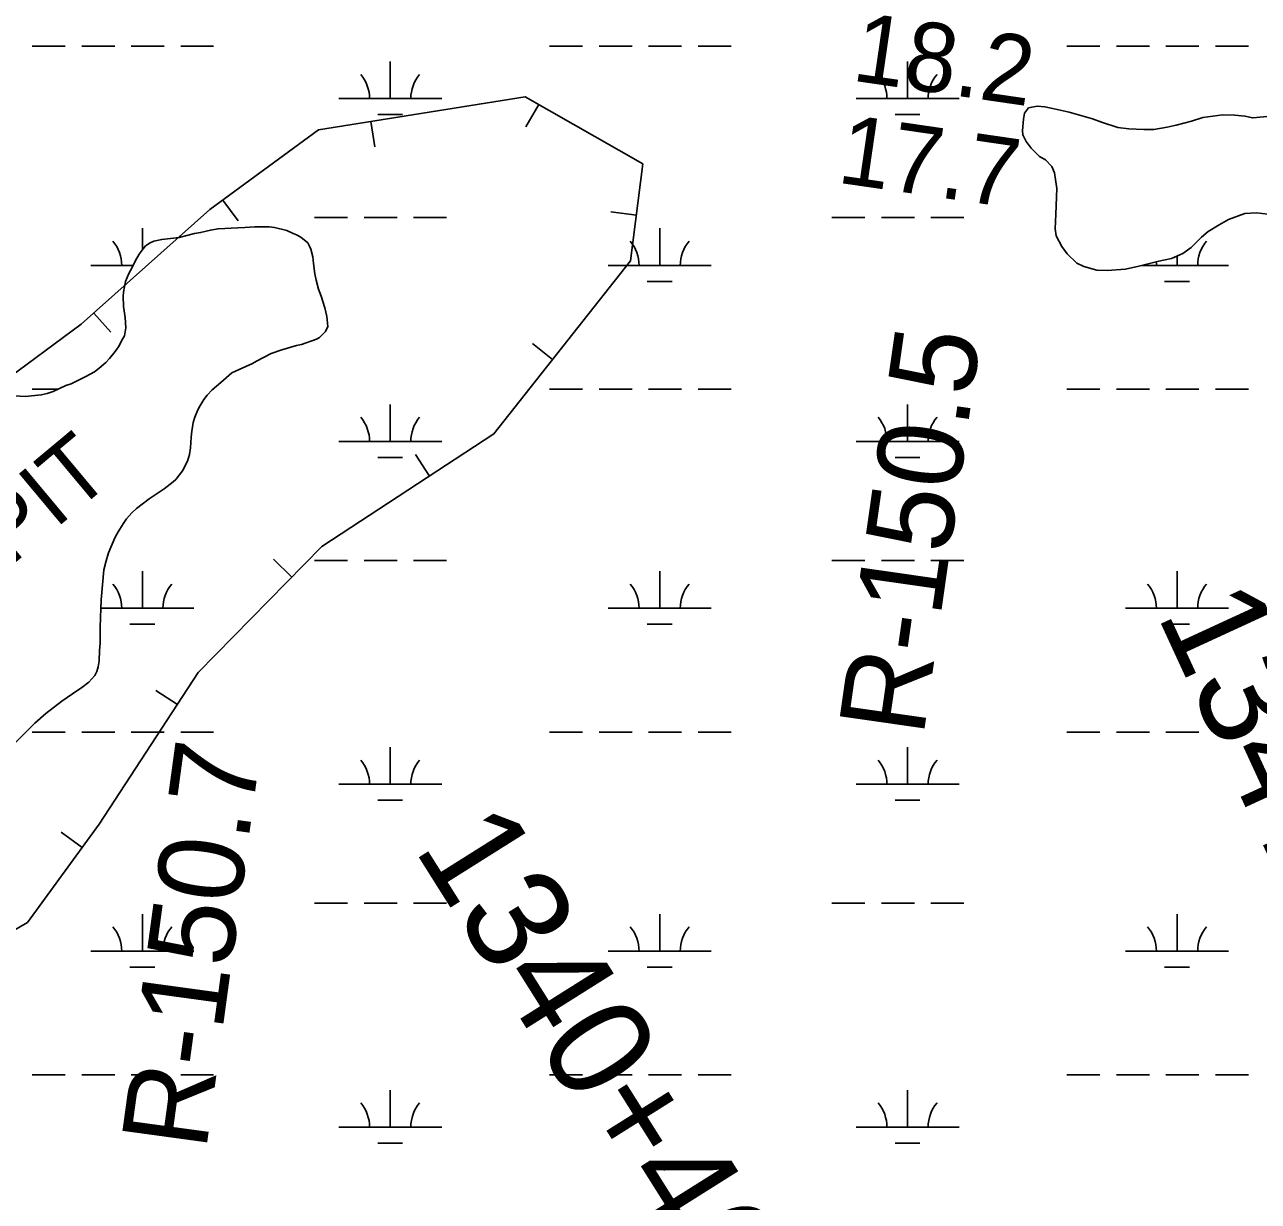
# Model space of a CAD drawing. Extents: x 3445503 to 3483459, y 540493 to 566012.
# Drawn here: x 3468436 to 3469633, y 548187 to 549328 of the extents above; entities that cross this region are included whole.
import ezdxf

# ---------------------------------------------------------------- set-up
doc = ezdxf.new("R2010")
doc.units = 0
for name, color, linetype in [('V-BORW-IDEN', 7, 'Continuous'), ('V-BORW-LINE', 7, 'Continuous'), ('V-RIVR-RANG', 7, 'Continuous'), ('V-RIVR-RANG-IDEN', 7, 'Continuous'), ('V-SITE-VEGE', 7, 'Continuous'), ('V-SURV-IDEN', 7, 'Continuous'), ('V-WETL-SWMP', 7, 'Continuous')]:
    doc.layers.add(name, color=color, linetype=linetype)

msp = doc.modelspace()

# ---------------------------------------------------------------- linework, layer by layer
at = {"layer": 'V-BORW-LINE'}
for p, q in [((3468934.5, 549250.7), (3468922.1, 549229)), ((3468771.8, 549234.3), (3468775.7, 549209.6)), ((3468628.1, 549158.1), (3468642.9, 549137.9)), ((3469029.3, 549143.4), (3469004.5, 549146.6)), ((3468502.8, 549048.5), (3468519.4, 549029.8)), ((3468948, 549003.4), (3468928.4, 549018.9)), ((3468828.6, 548890.3), (3468814.9, 548911.2)), ((3468694.9, 548792.1), (3468677.1, 548809.6)), ((3468584, 548668.6), (3468563, 548682.3)), ((3468491.6, 548529.9), (3468471.4, 548544.7))]:
    msp.add_line(p, q, dxfattribs=at)
for points in [[(3468333.1, 548921.3), (3468490.6, 549037.6), (3468615.6, 549148.9), (3468720.8, 549226.1), (3468921.3, 549258.2), (3469035.7, 549193.1), (3469023.6, 549099.2), (3468891.1, 548931.2), (3468724.2, 548822), (3468604.3, 548699.7), (3468508.1, 548552.5), (3468438.6, 548457.1), (3468325.2, 548391.8)], [(3468325.2, 548391.8), (3468438.6, 548457.1), (3468508.1, 548552.5), (3468604.3, 548699.7), (3468724.2, 548822), (3468891.1, 548931.2), (3469023.6, 549099.2), (3469035.7, 549193.1), (3468921.3, 549258.2), (3468720.8, 549226.1), (3468615.6, 549148.9), (3468490.6, 549037.6), (3468333.1, 548921.3)]]:
    msp.add_lwpolyline(points, dxfattribs=at)
at = {"layer": 'V-SITE-VEGE'}
for points in [[(3469668.4, 549241.9), (3469627.2, 549237.8), (3469619.6, 549239.5), (3469609.9, 549240.3), (3469598.2, 549240.7), (3469579, 549238.1), (3469567.8, 549234.7), (3469553, 549230.8), (3469544.2, 549228.8), (3469531.2, 549226.7), (3469521.7, 549226.6), (3469507.1, 549227.2), (3469496.5, 549228.6), (3469480.6, 549233.6), (3469471.9, 549236.8), (3469449.1, 549243.5), (3469434.7, 549246.5), (3469425.5, 549248.6), (3469418.2, 549249.2), (3469409.8, 549247.6), (3469405.9, 549242.5), (3469404.8, 549236.7), (3469404, 549225.7), (3469404.3, 549221.3), (3469407.6, 549214.9), (3469412.3, 549208.3), (3469420.5, 549200.4), (3469426.1, 549197.2), (3469432.3, 549190.6), (3469435, 549184.4), (3469437.3, 549169.4), (3469436.2, 549144.5), (3469435.7, 549130.1), (3469436.6, 549123.5), (3469442, 549113.1), (3469447.1, 549105.9), (3469456.5, 549096.9), (3469463.3, 549093.7), (3469476, 549090), (3469485.9, 549089.6), (3469503.8, 549090.9), (3469516.6, 549093.9), (3469536, 549098.7), (3469548.3, 549101.4), (3469559.3, 549106.3), (3469567.6, 549112.2), (3469577.5, 549122.2), (3469584.1, 549127.7), (3469594.6, 549134.2), (3469603.6, 549139.2), (3469619.5, 549145), (3469631, 549145.8), (3469647.3, 549143.9)], [(3468716.1, 549096.6), (3468715.4, 549103), (3468713.5, 549110.5), (3468712.2, 549113.5), (3468710.4, 549116.6), (3468703.7, 549122.1), (3468699.7, 549124.3), (3468696.2, 549125.6), (3468690.2, 549128.4), (3468678.2, 549131.4), (3468672.9, 549132.2), (3468659, 549132.1), (3468649.5, 549131.4), (3468642.7, 549131.3), (3468623.5, 549130.3), (3468616, 549128.9), (3468606.5, 549126.6), (3468600.6, 549125.7), (3468585.6, 549121.8), (3468568.8, 549119.9), (3468561.1, 549118.3), (3468557.6, 549116.7), (3468553.2, 549113.6), (3468550.8, 549110.7), (3468546.8, 549105.6), (3468543.4, 549099.6), (3468540.1, 549092.7), (3468536.8, 549086.8), (3468533.6, 549079), (3468532.7, 549073.9), (3468531.7, 549068.6), (3468531.5, 549064.9), (3468531.6, 549054.9), (3468533.2, 549044.1), (3468533.9, 549034), (3468532.7, 549026.4), (3468530.9, 549023.1), (3468526.8, 549015.8), (3468523.7, 549011.1), (3468518.3, 549004.2), (3468514.6, 549000.5), (3468508.2, 548994.9), (3468503.6, 548991.5), (3468495.2, 548986.8), (3468480.9, 548979.9), (3468475.9, 548978.1), (3468463.5, 548972.2), (3468457.8, 548970.4), (3468451.9, 548969), (3468436.4, 548967.4), (3468426, 548968)], [(3468424.1, 548628.8), (3468445.8, 548650.4), (3468456.3, 548659.9), (3468471.9, 548672), (3468482.2, 548678.9), (3468491.2, 548685.2), (3468498, 548690.3), (3468503.9, 548696.7), (3468505.7, 548700.5), (3468507, 548705.2), (3468508.2, 548711.1), (3468508.6, 548720.9), (3468509, 548728.1), (3468509.1, 548737.9), (3468509.1, 548743.4), (3468509.4, 548753.1), (3468509.6, 548761.3), (3468510, 548770.3), (3468512.8, 548799.3), (3468515, 548808.1), (3468517.3, 548815.7), (3468519.7, 548821.9), (3468523.8, 548830.9), (3468526.5, 548836.3), (3468531.3, 548844), (3468534.5, 548848.9), (3468539.8, 548854.5), (3468544.2, 548858.9), (3468556.7, 548868.3), (3468565.2, 548874.1), (3468571.2, 548877.9), (3468580, 548884.8), (3468582.4, 548887.1), (3468588.9, 548895.5), (3468593.7, 548904.8), (3468595.6, 548911.2), (3468596.7, 548917.6), (3468597.3, 548928), (3468597.9, 548934), (3468599.4, 548942.4), (3468600.9, 548947.5), (3468603.9, 548954.4), (3468605.9, 548958.1), (3468609.6, 548964.6), (3468612.9, 548968.8), (3468617.9, 548974.1), (3468626, 548981), (3468636.7, 548990.4), (3468643.8, 548993.8), (3468657, 548999.4), (3468660.9, 549001.8), (3468675, 549009.2), (3468685.2, 549012.6), (3468699.5, 549016.9), (3468704.3, 549017.9), (3468719.1, 549023.1), (3468721.9, 549024.6), (3468727.8, 549030.6), (3468729.8, 549035.3), (3468729.1, 549045.2), (3468727, 549053.4), (3468723.6, 549064.8), (3468720.9, 549071.7), (3468718.6, 549080.5), (3468717.5, 549086.6), (3468716.1, 549096.6)]]:
    msp.add_lwpolyline(points, dxfattribs=at)
at = {"layer": 'V-WETL-SWMP'}
for p, q in [((3468443.2, 549307.3), (3468475.2, 549307.3)), ((3468491.2, 549307.3), (3468523.2, 549307.3)), ((3468539.2, 549307.3), (3468571.2, 549307.3)), ((3468587.2, 549307.3), (3468619.2, 549307.3)), ((3468945.1, 549307.3), (3468977.1, 549307.3)), ((3468993.1, 549307.3), (3469025.1, 549307.3)), ((3469041.1, 549307.3), (3469073.1, 549307.3)), ((3469089.1, 549307.3), (3469121.1, 549307.3)), ((3469447, 549307.3), (3469479, 549307.3)), ((3469495, 549307.3), (3469527, 549307.3)), ((3469543, 549307.3), (3469575, 549307.3)), ((3469591, 549307.3), (3469623, 549307.3)), ((3468790.5, 549256.5), (3468790.5, 549292.5)), ((3469292.4, 549256.5), (3469292.4, 549292.5)), ((3468740.5, 549256.5), (3468840.5, 549256.5)), ((3469242.4, 549256.5), (3469342.4, 549256.5)), ((3468778.5, 549241.1), (3468802.5, 549241.1)), ((3469280.4, 549241.1), (3469304.4, 549241.1)), ((3468717.1, 549141.1), (3468749.1, 549141.1)), ((3468765.1, 549141.1), (3468797.1, 549141.1)), ((3468813.1, 549141.1), (3468845.1, 549141.1)), ((3469219, 549141.1), (3469251, 549141.1)), ((3469267, 549141.1), (3469299, 549141.1)), ((3469315, 549141.1), (3469347, 549141.1)), ((3468550, 549109.7), (3468550, 549130.7)), ((3469051.9, 549094.7), (3469051.9, 549130.7)), ((3468500, 549094.7), (3468541, 549094.7)), ((3469001.9, 549094.7), (3469101.9, 549094.7)), ((3469519.8, 549094.7), (3469603.8, 549094.7)), ((3469553.8, 549094.7), (3469553.8, 549103.9)), ((3469039.9, 549079.2), (3469063.9, 549079.2)), ((3469541.8, 549079.2), (3469565.8, 549079.2)), ((3468443.2, 548974.6), (3468468.5, 548974.6)), ((3468618.4, 548974.6), (3468619.2, 548974.6)), ((3468945.1, 548974.6), (3468977.1, 548974.6)), ((3468993.1, 548974.6), (3469025.1, 548974.6)), ((3469041.1, 548974.6), (3469073.1, 548974.6)), ((3469089.1, 548974.6), (3469121.1, 548974.6)), ((3469447, 548974.6), (3469479, 548974.6)), ((3469495, 548974.6), (3469527, 548974.6)), ((3469543, 548974.6), (3469575, 548974.6)), ((3469591, 548974.6), (3469623, 548974.6)), ((3468790.5, 548923.8), (3468790.5, 548959.8)), ((3469292.4, 548923.8), (3469292.4, 548959.8)), ((3468740.5, 548923.8), (3468840.5, 548923.8)), ((3469242.4, 548923.8), (3469342.4, 548923.8)), ((3468778.5, 548908.4), (3468802.5, 548908.4)), ((3469280.4, 548908.4), (3469304.4, 548908.4)), ((3468717.1, 548808.4), (3468749.1, 548808.4)), ((3468765.1, 548808.4), (3468797.1, 548808.4)), ((3468813.1, 548808.4), (3468845.1, 548808.4)), ((3469219, 548808.4), (3469251, 548808.4)), ((3469267, 548808.4), (3469299, 548808.4)), ((3469315, 548808.4), (3469347, 548808.4)), ((3468550, 548762), (3468550, 548798)), ((3469051.9, 548762), (3469051.9, 548798)), ((3469553.8, 548762), (3469553.8, 548798)), ((3468509.6, 548762), (3468600, 548762)), ((3469001.9, 548762), (3469101.9, 548762)), ((3469503.8, 548762), (3469603.8, 548762)), ((3468538, 548746.5), (3468562, 548746.5)), ((3469039.9, 548746.5), (3469063.9, 548746.5)), ((3469541.8, 548746.5), (3469565.8, 548746.5)), ((3468443.2, 548641.9), (3468475.2, 548641.9)), ((3468491.2, 548641.9), (3468523.2, 548641.9)), ((3468539.2, 548641.9), (3468571.2, 548641.9)), ((3468587.2, 548641.9), (3468619.2, 548641.9)), ((3468945.1, 548641.9), (3468977.1, 548641.9)), ((3468993.1, 548641.9), (3469025.1, 548641.9)), ((3469041.1, 548641.9), (3469073.1, 548641.9)), ((3469089.1, 548641.9), (3469121.1, 548641.9)), ((3469447, 548641.9), (3469479, 548641.9)), ((3469495, 548641.9), (3469527, 548641.9)), ((3469543, 548641.9), (3469575, 548641.9)), ((3469591, 548641.9), (3469623, 548641.9)), ((3468790.5, 548591.2), (3468790.5, 548627.2)), ((3469292.4, 548591.2), (3469292.4, 548627.2)), ((3468740.5, 548591.2), (3468840.5, 548591.2)), ((3469242.4, 548591.2), (3469342.4, 548591.2)), ((3468778.5, 548575.7), (3468802.5, 548575.7)), ((3469280.4, 548575.7), (3469304.4, 548575.7)), ((3468717.1, 548475.7), (3468749.1, 548475.7)), ((3468765.1, 548475.7), (3468797.1, 548475.7)), ((3468813.1, 548475.7), (3468845.1, 548475.7)), ((3469219, 548475.7), (3469251, 548475.7)), ((3469267, 548475.7), (3469299, 548475.7)), ((3469315, 548475.7), (3469347, 548475.7)), ((3468550, 548429.3), (3468550, 548465.3)), ((3469051.9, 548429.3), (3469051.9, 548465.3)), ((3469553.8, 548429.3), (3469553.8, 548465.3)), ((3468500, 548429.3), (3468600, 548429.3)), ((3469001.9, 548429.3), (3469101.9, 548429.3)), ((3469503.8, 548429.3), (3469603.8, 548429.3)), ((3468538, 548413.9), (3468562, 548413.9)), ((3469039.9, 548413.9), (3469063.9, 548413.9)), ((3469541.8, 548413.9), (3469565.8, 548413.9)), ((3468443.2, 548309.2), (3468475.2, 548309.2)), ((3468491.2, 548309.2), (3468523.2, 548309.2)), ((3468539.2, 548309.2), (3468571.2, 548309.2)), ((3468587.2, 548309.2), (3468619.2, 548309.2)), ((3468945.1, 548309.2), (3468977.1, 548309.2)), ((3468993.1, 548309.2), (3469025.1, 548309.2)), ((3469041.1, 548309.2), (3469073.1, 548309.2)), ((3469089.1, 548309.2), (3469121.1, 548309.2)), ((3469447, 548309.2), (3469479, 548309.2)), ((3469495, 548309.2), (3469527, 548309.2)), ((3469543, 548309.2), (3469575, 548309.2)), ((3469591, 548309.2), (3469623, 548309.2)), ((3468790.5, 548258.5), (3468790.5, 548294.5)), ((3469292.4, 548258.5), (3469292.4, 548294.5)), ((3468740.5, 548258.5), (3468840.5, 548258.5)), ((3469242.4, 548258.5), (3469342.4, 548258.5)), ((3468778.5, 548243.1), (3468802.5, 548243.1)), ((3469280.4, 548243.1), (3469304.4, 548243.1))]:
    msp.add_line(p, q, dxfattribs=at)
for points in [[(3469668.4, 549241.9), (3469627.2, 549237.8), (3469619.6, 549239.5), (3469609.9, 549240.3), (3469598.2, 549240.7), (3469579, 549238.1), (3469567.8, 549234.7), (3469553, 549230.8), (3469544.2, 549228.8), (3469531.2, 549226.7), (3469521.7, 549226.6), (3469507.1, 549227.2), (3469496.5, 549228.6), (3469480.6, 549233.6), (3469471.9, 549236.8), (3469449.1, 549243.5), (3469434.7, 549246.5), (3469425.5, 549248.6), (3469418.2, 549249.2), (3469409.8, 549247.6), (3469405.9, 549242.5), (3469404.8, 549236.7), (3469404, 549225.7), (3469404.3, 549221.3), (3469407.6, 549214.9), (3469412.3, 549208.3), (3469420.5, 549200.4), (3469426.1, 549197.2), (3469432.3, 549190.6), (3469435, 549184.4), (3469437.3, 549169.4), (3469436.2, 549144.5), (3469435.7, 549130.1), (3469436.6, 549123.5), (3469442, 549113.1), (3469447.1, 549105.9), (3469456.5, 549096.9), (3469463.3, 549093.7), (3469476, 549090), (3469485.9, 549089.6), (3469503.8, 549090.9), (3469516.6, 549093.9), (3469536, 549098.7), (3469548.3, 549101.4), (3469559.3, 549106.3), (3469567.6, 549112.2), (3469577.5, 549122.2), (3469584.1, 549127.7), (3469594.6, 549134.2), (3469603.6, 549139.2), (3469619.5, 549145), (3469631, 549145.8), (3469647.3, 549143.9)], [(3468617.9, 548974.1), (3468626, 548981), (3468636.7, 548990.4), (3468643.8, 548993.8), (3468657, 548999.4), (3468660.9, 549001.8), (3468675, 549009.2), (3468685.2, 549012.6), (3468699.5, 549016.9), (3468704.3, 549017.9), (3468719.1, 549023.1), (3468721.9, 549024.6), (3468727.8, 549030.6), (3468729.8, 549035.3), (3468729.1, 549045.2), (3468727, 549053.4), (3468723.6, 549064.8), (3468720.9, 549071.7), (3468718.6, 549080.5), (3468717.5, 549086.6), (3468716.1, 549096.6), (3468715.4, 549103), (3468713.5, 549110.5), (3468712.2, 549113.5), (3468710.4, 549116.6), (3468703.7, 549122.1), (3468699.7, 549124.3), (3468696.2, 549125.6), (3468690.2, 549128.4), (3468678.2, 549131.4), (3468672.9, 549132.2), (3468659, 549132.1), (3468649.5, 549131.4), (3468642.7, 549131.3), (3468623.5, 549130.3), (3468616, 549128.9), (3468606.5, 549126.6), (3468600.6, 549125.7), (3468585.6, 549121.8), (3468568.8, 549119.9), (3468561.1, 549118.3), (3468557.6, 549116.7), (3468553.2, 549113.6), (3468550.8, 549110.7), (3468546.8, 549105.6), (3468543.4, 549099.6), (3468540.1, 549092.7), (3468536.8, 549086.8), (3468533.6, 549079), (3468532.7, 549073.9), (3468531.7, 549068.6), (3468531.5, 549064.9), (3468531.6, 549054.9), (3468533.2, 549044.1), (3468533.9, 549034), (3468532.7, 549026.4), (3468530.9, 549023.1), (3468526.8, 549015.8), (3468523.7, 549011.1), (3468518.3, 549004.2), (3468514.6, 549000.5), (3468508.2, 548994.9), (3468503.6, 548991.5), (3468495.2, 548986.8), (3468480.9, 548979.9), (3468475.9, 548978.1), (3468463.5, 548972.2), (3468457.8, 548970.4), (3468451.9, 548969), (3468436.4, 548967.4), (3468426, 548968)], [(3468424.1, 548628.8), (3468445.8, 548650.4), (3468456.3, 548659.9), (3468471.9, 548672), (3468482.2, 548678.9), (3468491.2, 548685.2), (3468498, 548690.3), (3468503.9, 548696.7), (3468505.7, 548700.5), (3468507, 548705.2), (3468508.2, 548711.1), (3468508.6, 548720.9), (3468509, 548728.1), (3468509.1, 548737.9), (3468509.1, 548743.4), (3468509.5, 548753.1), (3468509.6, 548761.3), (3468510, 548770.3), (3468512.8, 548799.3), (3468515, 548808.1), (3468517.3, 548815.7), (3468519.7, 548821.9), (3468523.8, 548830.9), (3468526.5, 548836.3), (3468531.3, 548844), (3468534.5, 548848.9), (3468539.8, 548854.5), (3468544.2, 548858.9), (3468556.7, 548868.3), (3468565.2, 548874.1), (3468571.2, 548877.9), (3468580, 548884.8), (3468582.4, 548887.1), (3468588.9, 548895.5), (3468593.7, 548904.8), (3468595.6, 548911.2), (3468596.7, 548917.6), (3468597.3, 548928), (3468597.9, 548934), (3468599.4, 548942.4), (3468600.9, 548947.5), (3468603.9, 548954.4), (3468605.9, 548958.1), (3468609.6, 548964.6), (3468612.9, 548968.8), (3468617.9, 548974.1)]]:
    msp.add_lwpolyline(points, dxfattribs=at)
for centre, start, end in [((3468735.2, 549257), 359.2282, 40.7718), ((3468845.7, 549257), 139.2282, 180.7718), ((3469237.1, 549257), 359.2282, 40.7718), ((3469347.6, 549257), 139.2282, 180.7718), ((3468494.8, 549095.1), 359.2282, 40.7718), ((3468996.7, 549095.1), 359.2282, 40.7718), ((3469107.1, 549095.1), 139.2282, 180.7718), ((3469609.1, 549095.1), 139.2282, 180.7718), ((3469498.6, 549095.1), 359.2282, 4.8231), ((3468735.2, 548924.3), 359.2282, 40.7718), ((3468845.7, 548924.3), 139.2282, 180.7718), ((3469237.1, 548924.3), 359.2282, 40.7718), ((3469347.6, 548924.3), 139.2282, 180.7718), ((3468494.8, 548762.5), 359.2282, 40.7718), ((3468605.2, 548762.5), 139.2282, 180.7718), ((3468996.7, 548762.5), 359.2282, 40.7718), ((3469107.1, 548762.5), 139.2282, 180.7718), ((3469498.6, 548762.5), 359.2282, 40.7718), ((3469609.1, 548762.5), 139.2282, 180.7718), ((3468735.2, 548591.6), 359.2282, 40.7718), ((3468845.7, 548591.6), 139.2282, 180.7718), ((3469237.1, 548591.6), 359.2282, 40.7718), ((3469347.6, 548591.6), 139.2282, 180.7718), ((3468494.8, 548429.8), 359.2282, 40.7718), ((3468605.2, 548429.8), 139.2282, 180.7718), ((3468996.7, 548429.8), 359.2282, 40.7718), ((3469107.1, 548429.8), 139.2282, 180.7718), ((3469498.6, 548429.8), 359.2282, 40.7718), ((3469609.1, 548429.8), 139.2282, 180.7718), ((3468735.2, 548259), 359.2282, 40.7718), ((3468845.7, 548259), 139.2282, 180.7718), ((3469237.1, 548259), 359.2282, 40.7718), ((3469347.6, 548259), 139.2282, 180.7718)]:
    msp.add_arc(centre, 35.2, start, end, dxfattribs=at)

# ---------------------------------------------------------------- texts
at = {"layer": 'V-BORW-IDEN'}
msp.add_text('BORROW PIT', height=64, rotation=39.8726, dxfattribs=at).set_placement((3468100.4, 548533.6))
at = {"layer": 'V-RIVR-RANG'}
for s, p in [('18.2', (3469237.2, 549274.2)), ('17.7', (3469223, 549175.2))]:
    msp.add_text(s, height=67, rotation=351.7183, dxfattribs=at).set_placement(p)
at = {"layer": 'V-RIVR-RANG-IDEN'}
for s, rotation, p in [('R-150.5', 81.8564, (3469307.6, 548636.4)), ('R-150.7', 82.2255, (3468611.7, 548234.7))]:
    msp.add_text(s, height=83, rotation=rotation, dxfattribs=at).set_placement(p)
at = {"layer": 'V-SURV-IDEN'}
for s, rotation, p in [('1347+03.6', 294.739, (3469533.9, 548756.3)), ('1340+46.2', 302.1792, (3468812.8, 548529))]:
    msp.add_text(s, height=100, rotation=rotation, dxfattribs=at).set_placement(p)

doc.saveas('drawing.dxf')
